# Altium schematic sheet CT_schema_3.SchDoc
size 300 x 163 mm
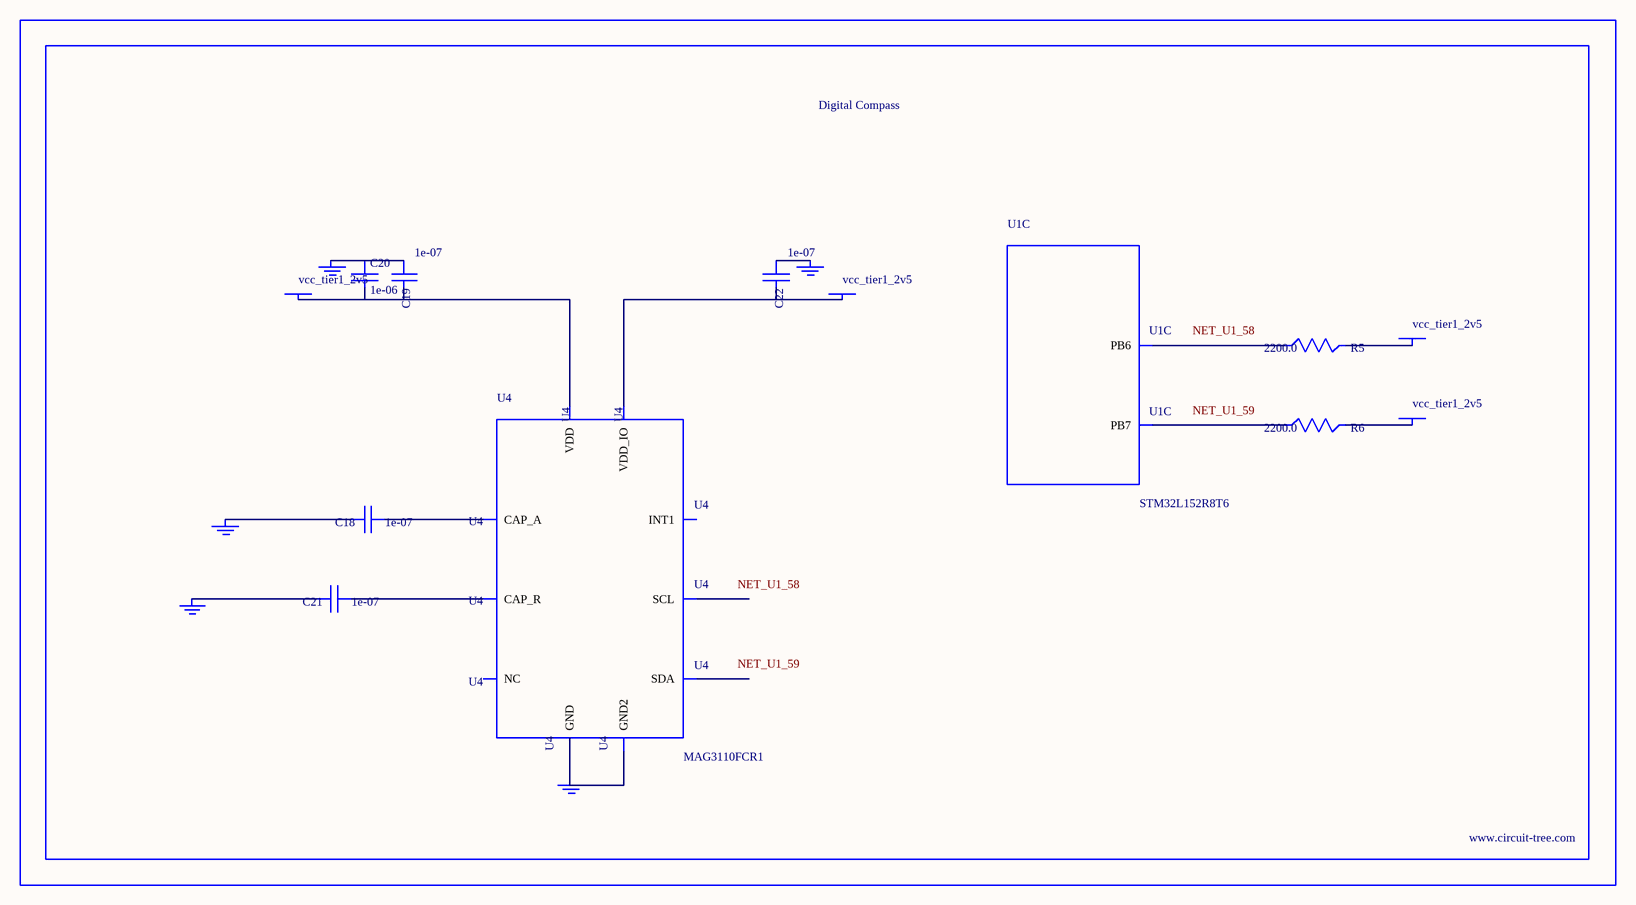
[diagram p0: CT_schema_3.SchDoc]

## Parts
BORDER2  (no value)
C18  1e-07  [C0402]
C19  1e-07  [C0402]
C20  1e-06  [C0603]
C21  1e-07  [C0402]
C22  1e-07  [C0402]
GND_INSTANCE_2_0  (no value)
GND_INSTANCE_2_1  (no value)
GND_INSTANCE_2_2  (no value)
GND_INSTANCE_2_3  (no value)
GND_INSTANCE_2_4  (no value)
POWER_INSTANCE_2_0  vcc_tier1_2v5
POWER_INSTANCE_2_1  vcc_tier1_2v5
POWER_INSTANCE_2_2  vcc_tier1_2v5
POWER_INSTANCE_2_3  vcc_tier1_2v5
R5  2200.0  [R0603]
R6  2200.0  [R0603]
U1  STM32L152R8T6  [LQFP64]  (part C of 6)
U4  MAG3110FCR1  [DFN-10]

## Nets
NetC18_1: C18.1 U4.1(CAP_A)
NetC18_2: C18.2 GND_INSTANCE_2_0.0(GND)
NetC19_1: C19.1 C20.1 GND_INSTANCE_2_1.0(GND)
NetC19_2: C19.2 C20.2 POWER_INSTANCE_2_0.0(PWR) U4.2(VDD)
NetC21_1: C21.1 U4.4(CAP_R)
NetC21_2: C21.2 GND_INSTANCE_2_2.0(GND)
NetC22_1: C22.1 GND_INSTANCE_2_3.0(GND)
NetC22_2: C22.2 POWER_INSTANCE_2_1.0(PWR) U4.8(VDD_IO)
NetGND_INSTANCE_2_4_0: GND_INSTANCE_2_4.0(GND) U4.5(GND) U4.10(GND2)
NetPOWER_INSTANCE_2_2_0: POWER_INSTANCE_2_2.0(PWR) R5.2
NetPOWER_INSTANCE_2_3_0: POWER_INSTANCE_2_3.0(PWR) R6.2
NetR5_1: R5.1 U1.58(PB6)
NetR6_1: R6.1 U1.59(PB7)

Not connected (* = marked no-connect by the designer): U4 3(NC) 6(SDA) 7(SCL) 9(INT1)

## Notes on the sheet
- Labels drawn without touching a wire or pin: NET_U1_58, NET_U1_59

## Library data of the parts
BORDER2 = BORDER_PAGE2
C18 C19 C21 C22 = C0402C104K3RACTU
C20 = C0603C105K3RACTU
GND_INSTANCE_2_0-GND_INSTANCE_2_4 = GND
POWER_INSTANCE_2_0-POWER_INSTANCE_2_3 = PWR
R5 R6 = RC0603JR-072K2L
